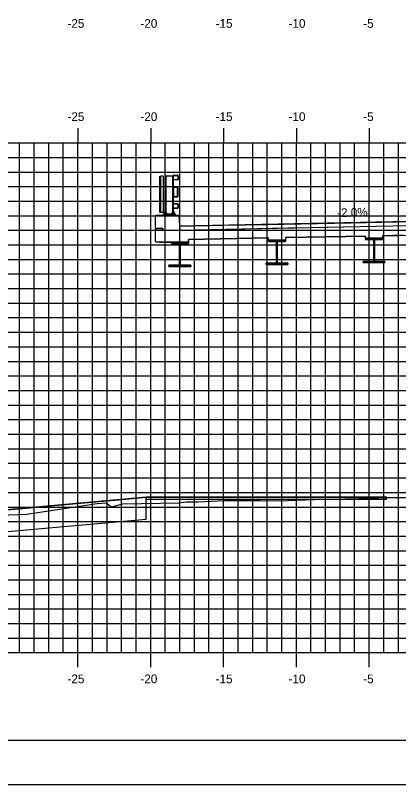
# Model space of a CAD drawing. Extents: x -22 to 1480, y -1511 to 8.
# Drawn here: x 824.1 to 850.4, y -1511.4 to -1458.6 of the extents above; entities that cross this region are included whole.
import ezdxf

# ---------------------------------------------------------------- set-up
doc = ezdxf.new("R2010")
doc.units = 0
for name, color, linetype in [('ANNOTATION', 7, 'Continuous'), ('BORDER', 7, 'Continuous'), ('D_Bridge_Deck', 7, 'Continuous'), ('D_Bridge_Railing', 7, 'Continuous'), ('D_Bridge_Superstructure', 7, 'Continuous'), ('D_Bridge_Superstructure_Slab', 7, 'Continuous'), ('D_Roadway_Centerline', 7, 'Continuous'), ('D_Roadway_Edge_Shoulder', 7, 'Continuous'), ('D_Roadway_SlopeLines', 7, 'Continuous'), ('H_V ANNOTATION', 7, 'Continuous'), ('MAJOR', 7, 'Continuous'), ('MINOR', 7, 'Continuous'), ('PLOT BOUNDARY', 7, 'Continuous'), ('S_Roadway_Centerline', 7, 'Continuous')]:
    doc.layers.add(name, color=color, linetype=linetype)

msp = doc.modelspace()

# ---------------------------------------------------------------- linework, layer by layer
at = {"layer": 'BORDER'}
msp.add_line((778.426, -1508.331), (938.426, -1508.331), dxfattribs=at)
at = {"layer": 'D_Bridge_Deck'}
for p, q in [((834.259, -1473.213), (833.801, -1473.213)), ((834.259, -1473.338), (834.259, -1473.213))]:
    msp.add_line(p, q, dxfattribs=at)
for points in [[(833.801, -1473.213), (833.759, -1473.172), (833.759, -1472.336), (833.801, -1472.294), (835.301, -1472.294), (835.346, -1472.336), (835.426, -1473.315)], [(834.051, -1474.148), (834.759, -1474.148), (836.009, -1474.148)]]:
    msp.add_lwpolyline(points, dxfattribs=at)
at = {"layer": 'D_Bridge_Railing'}
for p, q in [((834.103, -1469.627), (834.103, -1472.119)), ((834.269, -1469.627), (834.103, -1469.627)), ((834.269, -1469.627), (834.269, -1472.119)), ((834.474, -1469.586), (834.474, -1472.118)), ((834.929, -1469.586), (834.929, -1472.118)), ((834.967, -1469.836), (834.967, -1469.586)), ((834.988, -1469.836), (834.988, -1469.586)), ((835.009, -1469.544), (835.259, -1469.544)), ((835.009, -1469.565), (835.259, -1469.565)), ((835.28, -1469.586), (835.28, -1469.836)), ((835.301, -1469.586), (835.301, -1469.836)), ((835.259, -1469.857), (835.009, -1469.857)), ((835.259, -1469.877), (835.009, -1469.877)), ((834.967, -1470.429), (834.967, -1470.992)), ((834.993, -1470.429), (834.993, -1470.992)), ((835.249, -1470.377), (835.019, -1470.377)), ((835.249, -1470.403), (835.019, -1470.403)), ((835.275, -1470.992), (835.275, -1470.429)), ((835.301, -1470.992), (835.301, -1470.429)), ((835.019, -1471.018), (835.249, -1471.018)), ((835.019, -1471.044), (835.249, -1471.044)), ((834.967, -1471.794), (834.967, -1471.544)), ((834.988, -1471.794), (834.988, -1471.544)), ((835.009, -1471.502), (835.259, -1471.502)), ((835.009, -1471.523), (835.259, -1471.523)), ((835.259, -1471.815), (835.009, -1471.815)), ((835.259, -1471.836), (835.009, -1471.836)), ((835.28, -1471.544), (835.28, -1471.794)), ((835.301, -1471.544), (835.301, -1471.794)), ((834.269, -1472.119), (834.103, -1472.119)), ((834.4, -1472.044), (834.473, -1472.044)), ((834.4, -1472.052), (834.473, -1472.052)), ((834.4, -1472.06), (834.473, -1472.06)), ((834.4, -1472.069), (834.473, -1472.069)), ((834.4, -1472.077), (834.473, -1472.077)), ((834.4, -1472.085), (834.473, -1472.085)), ((834.4, -1472.094), (834.473, -1472.094)), ((834.4, -1472.102), (834.473, -1472.102)), ((834.4, -1472.11), (834.473, -1472.11)), ((834.402, -1472.125), (834.402, -1472.181)), ((834.418, -1472.048), (834.454, -1472.048)), ((834.418, -1472.056), (834.454, -1472.056)), ((834.418, -1472.065), (834.454, -1472.065)), ((834.418, -1472.073), (834.454, -1472.073)), ((834.418, -1472.081), (834.454, -1472.081)), ((834.418, -1472.089), (834.454, -1472.089)), ((834.418, -1472.098), (834.454, -1472.098)), ((834.418, -1472.106), (834.454, -1472.106)), ((834.418, -1472.114), (834.454, -1472.114)), ((834.471, -1472.125), (834.471, -1472.181)), ((834.931, -1472.044), (835.004, -1472.044)), ((834.931, -1472.052), (835.004, -1472.052)), ((834.931, -1472.06), (835.004, -1472.06)), ((834.931, -1472.069), (835.004, -1472.069)), ((834.931, -1472.077), (835.004, -1472.077)), ((834.931, -1472.085), (835.004, -1472.085)), ((834.931, -1472.094), (835.004, -1472.094)), ((834.931, -1472.102), (835.004, -1472.102)), ((834.931, -1472.11), (835.004, -1472.11)), ((834.933, -1472.125), (834.933, -1472.181)), ((834.949, -1472.048), (834.986, -1472.048)), ((834.949, -1472.056), (834.986, -1472.056)), ((834.949, -1472.065), (834.986, -1472.065)), ((834.949, -1472.073), (834.986, -1472.073)), ((834.949, -1472.081), (834.986, -1472.081)), ((834.949, -1472.089), (834.986, -1472.089)), ((834.949, -1472.098), (834.986, -1472.098)), ((834.949, -1472.106), (834.986, -1472.106)), ((834.949, -1472.114), (834.986, -1472.114)), ((835.002, -1472.125), (835.002, -1472.181))]:
    msp.add_line(p, q, dxfattribs=at)
for points in [[(834.019, -1469.627), (834.019, -1472.119)], [(834.436, -1472.036), (834.436, -1469.586), (834.967, -1469.586), (834.967, -1472.036)], [(834.4, -1472.118), (834.4, -1472.044), (834.408, -1472.036), (834.464, -1472.036), (834.473, -1472.044), (834.473, -1472.118)], [(834.931, -1472.118), (834.931, -1472.044), (834.939, -1472.036), (834.996, -1472.036), (835.004, -1472.044), (835.004, -1472.118)]]:
    msp.add_lwpolyline(points, dxfattribs=at)
for points in [[(834.292, -1472.202), (835.112, -1472.202), (835.112, -1472.284), (834.292, -1472.284)], [(834.292, -1472.284), (835.112, -1472.284), (835.112, -1472.294), (834.292, -1472.294)], [(834.363, -1472.202), (834.509, -1472.202), (834.509, -1472.189), (834.363, -1472.189)], [(834.367, -1472.125), (834.381, -1472.118), (834.491, -1472.118), (834.505, -1472.125), (834.505, -1472.181), (834.491, -1472.189), (834.381, -1472.189), (834.367, -1472.181)], [(834.895, -1472.202), (835.04, -1472.202), (835.04, -1472.189), (834.895, -1472.189)], [(834.899, -1472.125), (834.912, -1472.118), (835.023, -1472.118), (835.036, -1472.125), (835.036, -1472.181), (835.023, -1472.189), (834.912, -1472.189), (834.899, -1472.181)]]:
    msp.add_lwpolyline(points, close=True, dxfattribs=at)
for centre, radius, start, end in [((835.009, -1469.586), 0.0417, 90, 180), ((835.009, -1469.586), 0.0208, 90, 180), ((835.259, -1469.586), 0.0417, 0, 90), ((835.259, -1469.586), 0.0208, 0, 90), ((835.009, -1469.836), 0.0417, 180, 270), ((835.009, -1469.836), 0.0208, 180, 270), ((835.259, -1469.836), 0.0417, 270, 0), ((835.259, -1469.836), 0.0208, 270, 0), ((835.019, -1470.429), 0.052, 90, 180), ((835.019, -1470.429), 0.026, 90, 180), ((835.249, -1470.429), 0.052, 0, 90), ((835.249, -1470.429), 0.026, 0, 90), ((835.019, -1470.992), 0.052, 180, 270), ((835.019, -1470.992), 0.026, 180, 270), ((835.249, -1470.992), 0.052, 270, 0), ((835.249, -1470.992), 0.026, 270, 0), ((835.009, -1471.544), 0.0417, 90, 180), ((835.009, -1471.794), 0.0417, 180, 270), ((835.009, -1471.544), 0.0208, 90, 180), ((835.009, -1471.794), 0.0208, 180, 270), ((835.259, -1471.544), 0.0417, 0, 90), ((835.259, -1471.544), 0.0208, 0, 90), ((835.259, -1471.794), 0.0417, 270, 0), ((835.259, -1471.794), 0.0208, 270, 0), ((834.385, -1472.15), 0.0302, 55.4339, 120), ((834.385, -1472.156), 0.0302, 240, 304.5661), ((834.436, -1472.234), 0.114, 72.412, 107.588), ((834.436, -1472.073), 0.114, 252.412, 287.588), ((834.488, -1472.15), 0.0302, 60, 124.5661), ((834.488, -1472.156), 0.0302, 235.4339, 300), ((834.916, -1472.15), 0.0302, 55.4339, 120), ((834.916, -1472.156), 0.0302, 240, 304.5661), ((834.967, -1472.234), 0.114, 72.412, 107.588), ((834.967, -1472.073), 0.114, 252.412, 287.588), ((835.019, -1472.15), 0.0302, 60, 124.5661), ((835.019, -1472.156), 0.0302, 235.4339, 300)]:
    msp.add_arc(centre, radius, start, end, dxfattribs=at)
at = {"layer": 'D_Bridge_Superstructure'}
for p, q in [((849.342, -1473.882), (848.176, -1473.882)), ((848.176, -1473.882), (848.176, -1473.965)), ((848.78, -1473.965), (848.738, -1473.965)), ((848.78, -1473.965), (848.738, -1473.965)), ((848.78, -1473.965), (849.342, -1473.965)), ((849.342, -1473.965), (849.342, -1473.882)), ((836.009, -1474.148), (834.842, -1474.148)), ((834.842, -1474.148), (834.842, -1474.232)), ((835.447, -1474.232), (835.405, -1474.232)), ((835.447, -1474.232), (835.405, -1474.232)), ((835.447, -1474.232), (836.009, -1474.232)), ((836.009, -1474.232), (836.009, -1474.148)), ((842.676, -1474.015), (841.509, -1474.015)), ((841.509, -1474.015), (841.509, -1474.098)), ((842.113, -1474.098), (842.072, -1474.098)), ((842.113, -1474.098), (842.072, -1474.098)), ((842.113, -1474.098), (842.676, -1474.098)), ((842.676, -1474.098), (842.676, -1474.015)), ((848.738, -1475.465), (848.009, -1475.465)), ((848.009, -1475.465), (848.009, -1475.548)), ((848.738, -1475.465), (848.009, -1475.465)), ((848.78, -1475.465), (848.738, -1475.465)), ((848.78, -1475.465), (848.738, -1475.465)), ((835.405, -1475.732), (834.676, -1475.732)), ((834.676, -1475.732), (834.676, -1475.815)), ((835.405, -1475.732), (834.676, -1475.732)), ((835.447, -1475.732), (835.405, -1475.732)), ((835.447, -1475.732), (835.405, -1475.732)), ((842.072, -1475.598), (841.342, -1475.598)), ((841.342, -1475.598), (841.342, -1475.682)), ((842.072, -1475.598), (841.342, -1475.598)), ((842.113, -1475.598), (842.072, -1475.598)), ((842.113, -1475.598), (842.072, -1475.598))]:
    msp.add_line(p, q, dxfattribs=at)
for points in [[(848.176, -1473.882), (849.342, -1473.882), (849.342, -1473.965), (848.176, -1473.965)], [(848.738, -1473.965), (848.78, -1473.965), (848.78, -1475.465), (848.738, -1475.465)], [(834.842, -1474.148), (836.009, -1474.148), (836.009, -1474.232), (834.842, -1474.232)], [(835.405, -1474.232), (835.447, -1474.232), (835.447, -1475.732), (835.405, -1475.732)], [(841.509, -1474.015), (842.676, -1474.015), (842.676, -1474.098), (841.509, -1474.098)], [(842.072, -1474.098), (842.113, -1474.098), (842.113, -1475.598), (842.072, -1475.598)], [(848.009, -1475.465), (849.509, -1475.465), (849.509, -1475.548), (848.009, -1475.548)], [(834.676, -1475.732), (836.176, -1475.732), (836.176, -1475.815), (834.676, -1475.815)], [(841.342, -1475.598), (842.842, -1475.598), (842.842, -1475.682), (841.342, -1475.682)]]:
    msp.add_lwpolyline(points, close=True, dxfattribs=at)
for points in [[(848.78, -1473.965), (849.342, -1473.965), (849.342, -1473.882), (848.176, -1473.882), (848.176, -1473.965), (848.738, -1473.965), (848.78, -1473.965)], [(848.176, -1473.965), (848.738, -1473.965), (848.78, -1473.965)], [(848.738, -1473.965), (848.738, -1475.465), (848.78, -1475.465), (848.78, -1473.965)], [(848.738, -1473.965), (848.738, -1475.465), (848.78, -1475.465), (848.78, -1473.965)], [(835.447, -1474.232), (836.009, -1474.232), (836.009, -1474.148), (834.842, -1474.148), (834.842, -1474.232), (835.405, -1474.232), (835.447, -1474.232)], [(834.842, -1474.232), (835.405, -1474.232), (835.447, -1474.232)], [(835.405, -1474.232), (835.405, -1475.732), (835.447, -1475.732), (835.447, -1474.232)], [(835.405, -1474.232), (835.405, -1475.732), (835.447, -1475.732), (835.447, -1474.232)], [(842.113, -1474.098), (842.676, -1474.098), (842.676, -1474.015), (841.509, -1474.015), (841.509, -1474.098), (842.072, -1474.098), (842.113, -1474.098)], [(841.509, -1474.098), (842.072, -1474.098), (842.113, -1474.098)], [(842.072, -1474.098), (842.072, -1475.598), (842.113, -1475.598), (842.113, -1474.098)], [(842.072, -1474.098), (842.072, -1475.598), (842.113, -1475.598), (842.113, -1474.098)], [(848.009, -1475.465), (848.009, -1475.548), (849.509, -1475.548), (849.509, -1475.465), (848.78, -1475.465)], [(848.009, -1475.548), (849.509, -1475.548), (849.509, -1475.465), (848.78, -1475.465)], [(834.676, -1475.732), (834.676, -1475.815), (836.176, -1475.815), (836.176, -1475.732), (835.447, -1475.732)], [(834.676, -1475.815), (836.176, -1475.815), (836.176, -1475.732), (835.447, -1475.732)], [(841.342, -1475.598), (841.342, -1475.682), (842.842, -1475.682), (842.842, -1475.598), (842.113, -1475.598)], [(841.342, -1475.682), (842.842, -1475.682), (842.842, -1475.598), (842.113, -1475.598)]]:
    msp.add_lwpolyline(points, dxfattribs=at)
at = {"layer": 'D_Bridge_Superstructure_Slab'}
for points in [[(833.801, -1472.294), (835.301, -1472.294), (835.346, -1472.336), (835.426, -1473.315), (834.259, -1473.338), (834.259, -1473.213), (833.801, -1473.213), (833.759, -1473.172), (833.759, -1472.336)], [(835.404, -1473.045), (835.426, -1473.315), (853.426, -1472.955), (875.426, -1473.395), (875.448, -1473.125), (853.426, -1472.684)]]:
    msp.add_lwpolyline(points, close=True, dxfattribs=at)
for points in [[(850.759, -1473.675), (849.342, -1473.703), (849.342, -1473.882), (848.176, -1473.882), (848.176, -1473.727), (844.092, -1473.808), (842.759, -1473.835), (842.676, -1473.837), (842.676, -1474.015), (841.509, -1474.015), (841.509, -1473.86), (836.009, -1473.97), (836.009, -1474.148), (834.051, -1474.148), (834.009, -1474.107), (834.009, -1474.148), (833.801, -1474.148), (833.759, -1474.107), (833.759, -1473.255), (833.801, -1473.213), (834.259, -1473.213), (834.259, -1473.338), (853.426, -1472.955)], [(834.009, -1474.148), (833.801, -1474.148), (833.759, -1474.107), (833.759, -1473.255), (833.801, -1473.213)], [(834.259, -1473.338), (853.426, -1472.955), (876.593, -1473.418)], [(835.426, -1473.315), (843.926, -1473.145)], [(836.009, -1474.148), (836.009, -1473.97), (841.509, -1473.86)], [(842.676, -1473.837), (842.676, -1474.015), (841.509, -1474.015), (841.509, -1473.86)], [(842.676, -1473.837), (848.176, -1473.727)], [(849.342, -1473.703), (849.342, -1473.882), (848.176, -1473.882), (848.176, -1473.727)], [(849.342, -1473.703), (853.426, -1473.622), (854.842, -1473.65)], [(834.009, -1474.148), (834.009, -1474.107), (834.051, -1474.148)]]:
    msp.add_lwpolyline(points, dxfattribs=at)
at = {"layer": 'D_Roadway_Centerline'}
for points in [[(835.404, -1473.045), (838.426, -1472.984), (841.426, -1472.924), (847.186, -1472.809), (853.426, -1472.684), (859.186, -1472.799), (865.426, -1472.924), (870.426, -1473.024), (875.448, -1473.125)], [(820.973, -1492.75), (824.873, -1492.402), (826.842, -1492.226), (830.142, -1491.931), (830.177, -1491.928), (830.349, -1491.912), (830.982, -1491.856), (833.12, -1491.665), (834.887, -1491.659), (835.41, -1491.658), (838.898, -1491.648), (840.678, -1491.647), (842.897, -1491.648), (845.946, -1491.654), (849.622, -1491.666), (851.214, -1491.671)]]:
    msp.add_lwpolyline(points, dxfattribs=at)
at = {"layer": 'D_Roadway_Edge_Shoulder'}
msp.add_lwpolyline([(849.622, -1491.666), (833.12, -1491.665), (833.12, -1491.79), (849.622, -1491.791)], close=True, dxfattribs=at)
at = {"layer": 'D_Roadway_SlopeLines'}
msp.add_lwpolyline([(833.12, -1491.665), (816.911, -1493.115), (804.561, -1490.914), (804.561, -1492.414), (816.911, -1494.615), (833.12, -1493.165)], close=True, dxfattribs=at)
msp.add_lwpolyline([(833.12, -1491.665), (816.911, -1493.115)], dxfattribs=at)
msp.add_lwpolyline([(833.12, -1491.665), (816.911, -1493.115)], dxfattribs=at)
at = {"layer": 'MAJOR'}
for p, q in [((828.426, -1466.329), (828.426, -1467.331)), ((833.426, -1466.329), (833.426, -1467.331)), ((838.426, -1466.329), (838.426, -1467.331)), ((843.426, -1466.329), (843.426, -1467.331)), ((848.426, -1466.329), (848.426, -1467.331)), ((783.426, -1467.331), (923.426, -1467.331)), ((783.426, -1467.331), (923.426, -1467.331)), ((828.426, -1502.331), (828.426, -1467.331)), ((833.426, -1502.331), (833.426, -1467.331)), ((838.426, -1502.331), (838.426, -1467.331)), ((843.426, -1502.331), (843.426, -1467.331)), ((848.426, -1502.331), (848.426, -1467.331)), ((783.426, -1472.331), (923.426, -1472.331)), ((783.426, -1477.331), (923.426, -1477.331)), ((783.426, -1482.331), (923.426, -1482.331)), ((783.426, -1487.331), (923.426, -1487.331)), ((783.426, -1492.331), (923.426, -1492.331)), ((783.426, -1497.331), (923.426, -1497.331)), ((783.426, -1502.331), (923.426, -1502.331)), ((783.426, -1502.331), (923.426, -1502.331)), ((828.426, -1503.333), (828.426, -1502.331)), ((833.426, -1503.333), (833.426, -1502.331)), ((838.426, -1503.333), (838.426, -1502.331)), ((843.426, -1503.333), (843.426, -1502.331)), ((848.426, -1503.333), (848.426, -1502.331))]:
    msp.add_line(p, q, dxfattribs=at)
at = {"layer": 'MINOR'}
for p, q in [((824.426, -1502.331), (824.426, -1467.331)), ((825.426, -1502.331), (825.426, -1467.331)), ((826.426, -1502.331), (826.426, -1467.331)), ((827.426, -1502.331), (827.426, -1467.331)), ((829.426, -1502.331), (829.426, -1467.331)), ((830.426, -1502.331), (830.426, -1467.331)), ((831.426, -1502.331), (831.426, -1467.331)), ((832.426, -1502.331), (832.426, -1467.331)), ((834.426, -1502.331), (834.426, -1467.331)), ((835.426, -1502.331), (835.426, -1467.331)), ((836.426, -1502.331), (836.426, -1467.331)), ((837.426, -1502.331), (837.426, -1467.331)), ((839.426, -1502.331), (839.426, -1467.331)), ((840.426, -1502.331), (840.426, -1467.331)), ((841.426, -1502.331), (841.426, -1467.331)), ((842.426, -1502.331), (842.426, -1467.331)), ((844.426, -1502.331), (844.426, -1467.331)), ((845.426, -1502.331), (845.426, -1467.331)), ((846.426, -1502.331), (846.426, -1467.331)), ((847.426, -1502.331), (847.426, -1467.331)), ((849.426, -1502.331), (849.426, -1467.331)), ((850.426, -1502.331), (850.426, -1467.331)), ((783.426, -1468.331), (923.426, -1468.331)), ((783.426, -1469.331), (923.426, -1469.331)), ((783.426, -1470.331), (923.426, -1470.331)), ((783.426, -1471.331), (923.426, -1471.331)), ((783.426, -1473.331), (923.426, -1473.331)), ((783.426, -1474.331), (923.426, -1474.331)), ((783.426, -1475.331), (923.426, -1475.331)), ((783.426, -1476.331), (923.426, -1476.331)), ((783.426, -1478.331), (923.426, -1478.331)), ((783.426, -1479.331), (923.426, -1479.331)), ((783.426, -1480.331), (923.426, -1480.331)), ((783.426, -1481.331), (923.426, -1481.331)), ((783.426, -1483.331), (923.426, -1483.331)), ((783.426, -1484.331), (923.426, -1484.331)), ((783.426, -1485.331), (923.426, -1485.331)), ((783.426, -1486.331), (923.426, -1486.331)), ((783.426, -1488.331), (923.426, -1488.331)), ((783.426, -1489.331), (923.426, -1489.331)), ((783.426, -1490.331), (923.426, -1490.331)), ((783.426, -1491.331), (923.426, -1491.331)), ((783.426, -1493.331), (923.426, -1493.331)), ((783.426, -1494.331), (923.426, -1494.331)), ((783.426, -1495.331), (923.426, -1495.331)), ((783.426, -1496.331), (923.426, -1496.331)), ((783.426, -1498.331), (923.426, -1498.331)), ((783.426, -1499.331), (923.426, -1499.331)), ((783.426, -1500.331), (923.426, -1500.331)), ((783.426, -1501.331), (923.426, -1501.331))]:
    msp.add_line(p, q, dxfattribs=at)
at = {"layer": 'PLOT BOUNDARY'}
msp.add_lwpolyline([(770.333, -1511.39), (940.333, -1511.39), (940.333, -1401.39), (770.333, -1401.39)], close=True, dxfattribs=at)
at = {"layer": 'S_Roadway_Centerline'}
msp.add_lwpolyline([(823.058, -1492.887), (824.903, -1492.832), (829.756, -1492.089), (830.364, -1492.049), (830.723, -1492.328), (831.521, -1492.116), (835.363, -1492.038), (835.856, -1491.983), (836.403, -1491.979), (836.681, -1491.98), (838.507, -1491.887), (840.324, -1491.879), (840.951, -1491.876), (842.271, -1491.901), (844.658, -1491.824), (845.518, -1491.802), (846.752, -1491.767), (848.673, -1491.715), (849.068, -1491.701), (849.622, -1491.683), (850.915, -1491.685)], dxfattribs=at)
msp.add_lwpolyline([(823.058, -1492.887), (824.903, -1492.832), (829.756, -1492.089), (830.364, -1492.049), (830.723, -1492.328), (831.521, -1492.116), (835.363, -1492.038), (835.856, -1491.983), (836.403, -1491.979), (836.681, -1491.98), (838.507, -1491.887), (840.324, -1491.879), (840.951, -1491.876), (842.271, -1491.901), (844.658, -1491.824), (845.518, -1491.802), (846.752, -1491.767), (848.673, -1491.715), (849.068, -1491.701), (849.622, -1491.683), (850.915, -1491.685)], dxfattribs=at)

# ---------------------------------------------------------------- texts
at = {"layer": 'ANNOTATION'}
msp.add_text('-2.0%', height=0.6, rotation=1.1458, dxfattribs=at).set_placement((846.229, -1472.428))
at = {"layer": 'H_V ANNOTATION'}
for s, p in [('-25', (827.712, -1459.431)), ('-20', (832.72, -1459.431)), ('-15', (837.883, -1459.431)), ('-10', (842.891, -1459.431)), ('-5', (848.017, -1459.431)), ('-25', (827.712, -1465.831)), ('-20', (832.72, -1465.831)), ('-15', (837.883, -1465.831)), ('-10', (842.891, -1465.831)), ('-5', (848.017, -1465.831)), ('-25', (827.712, -1504.431)), ('-20', (832.72, -1504.431)), ('-15', (837.883, -1504.431)), ('-10', (842.891, -1504.431)), ('-5', (848.017, -1504.431))]:
    msp.add_text(s, height=0.6, dxfattribs=at).set_placement(p)

doc.saveas('drawing.dxf')
